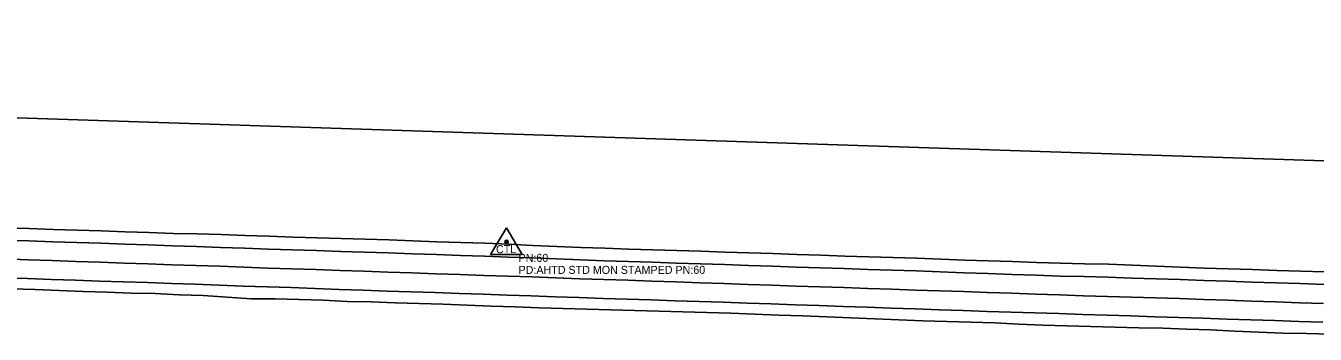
# Model space of a CAD drawing. Extents: x 976456 to 985170, y 1525951 to 1527080.
# Drawn here: x 980813 to 981619, y 1526356 to 1526549 of the extents above; entities that cross this region are included whole.
import ezdxf

# ---------------------------------------------------------------- set-up
doc = ezdxf.new("R2010")
doc.units = 0
for name, color, linetype in [('S_EDGE_PAVEMENT', 7, 'Continuous'), ('S_FIBER_OPTIC_CABLE', 7, 'Continuous'), ('S_PAVEMENT_CROWN', 7, 'Continuous'), ('S_PRIMARY_CTL', 7, 'Continuous'), ('S_PRIMARY_CTL_ANNOT', 7, 'Continuous'), ('S_SHOULDER', 7, 'Continuous')]:
    doc.layers.add(name, color=color, linetype=linetype)

msp = doc.modelspace()

# ---------------------------------------------------------------- linework, layer by layer
at = {"layer": 'S_EDGE_PAVEMENT'}
for points in [[(980799.88, 1526414.86), (980814.87, 1526414.33), (980829.86, 1526413.87), (980829.86, 1526413.87), (980844.85, 1526413.33), (980844.85, 1526413.33), (980859.84, 1526412.94), (980874.84, 1526412.4), (980874.84, 1526412.4), (980889.81, 1526411.88), (980904.8, 1526411.37), (980919.79, 1526410.8), (980919.79, 1526410.8), (980934.78, 1526410.32), (980949.77, 1526409.81), (980964.76, 1526409.28), (980964.76, 1526409.28), (980979.76, 1526408.77), (980994.75, 1526408.3), (980994.75, 1526408.3), (981009.74, 1526407.81), (981024.73, 1526407.32), (981039.68, 1526406.84), (981054.67, 1526406.31), (981069.66, 1526405.78), (981084.66, 1526405.32), (981099.65, 1526404.85), (981114.64, 1526404.28), (981114.64, 1526404.28), (981129.63, 1526403.7), (981144.62, 1526403.14), (981159.68, 1526402.54), (981174.67, 1526401.99), (981189.66, 1526401.51), (981204.65, 1526401.01), (981219.65, 1526400.55), (981234.64, 1526400.06), (981249.63, 1526399.55), (981264.62, 1526399.1), (981279.61, 1526398.56), (981294.6, 1526398.01), (981309.59, 1526397.5), (981324.54, 1526397.04), (981339.53, 1526396.61), (981354.52, 1526396.11), (981369.52, 1526395.62), (981384.51, 1526395.13), (981399.49, 1526394.52), (981414.49, 1526393.99), (981429.47, 1526393.42), (981444.47, 1526392.93), (981459.46, 1526392.44), (981474.43, 1526392.06), (981489.42, 1526391.62), (981504.41, 1526391.12), (981519.41, 1526390.68), (981519.41, 1526390.68), (981534.4, 1526390.2), (981534.4, 1526390.2), (981549.39, 1526389.63), (981564.38, 1526389.15), (981579.37, 1526388.69), (981594.45, 1526388.2), (981609.44, 1526387.73), (981624.43, 1526387.21)], [(980799.04, 1526391.32), (980814.03, 1526390.79), (980829.02, 1526390.26), (980844.01, 1526389.8), (980859, 1526389.31), (980859, 1526389.31), (980873.99, 1526388.82), (980889, 1526388.32), (980889, 1526388.32), (980903.99, 1526387.78), (980918.98, 1526387.26), (980933.97, 1526386.71), (980948.96, 1526386.18), (980963.96, 1526385.69), (980978.95, 1526385.17), (980978.95, 1526385.17), (980993.94, 1526384.64), (981008.93, 1526384.1), (981008.93, 1526384.1), (981023.92, 1526383.58), (981023.92, 1526383.58), (981038.95, 1526383.07), (981053.94, 1526382.58), (981053.94, 1526382.58), (981068.93, 1526382.07), (981068.93, 1526382.07), (981083.92, 1526381.59), (981083.92, 1526381.59), (981098.91, 1526381.01), (981098.91, 1526381.01), (981113.9, 1526380.49), (981113.9, 1526380.49), (981128.89, 1526379.96), (981143.88, 1526379.46), (981143.88, 1526379.46), (981158.81, 1526378.95), (981158.81, 1526378.95), (981173.8, 1526378.44), (981188.8, 1526377.95), (981203.79, 1526377.46), (981218.78, 1526376.96), (981233.77, 1526376.52), (981248.77, 1526376.02), (981263.76, 1526375.47), (981263.76, 1526375.47), (981278.75, 1526374.96), (981293.74, 1526374.44), (981293.74, 1526374.44), (981308.73, 1526373.92), (981323.76, 1526373.43), (981323.76, 1526373.43), (981338.76, 1526372.95), (981338.76, 1526372.95), (981353.75, 1526372.45), (981368.74, 1526371.96), (981383.73, 1526371.4), (981398.72, 1526370.85), (981398.72, 1526370.85), (981413.71, 1526370.34), (981428.7, 1526369.85), (981443.7, 1526369.39), (981458.69, 1526368.92), (981458.69, 1526368.92), (981473.7, 1526368.46), (981473.7, 1526368.46), (981488.7, 1526368.01), (981488.7, 1526368.01), (981503.69, 1526367.51), (981518.68, 1526367.03), (981533.67, 1526366.53), (981548.67, 1526366.05), (981563.66, 1526365.57), (981578.65, 1526365.1), (981593.58, 1526364.6), (981593.58, 1526364.6), (981608.57, 1526364.09), (981608.57, 1526364.09), (981623.56, 1526363.57)]]:
    msp.add_lwpolyline(points, dxfattribs=at)
at = {"layer": 'S_FIBER_OPTIC_CABLE'}
msp.add_line((982227.16, 1526444.43), (979068.74, 1526548.75), dxfattribs=at)
at = {"layer": 'S_PAVEMENT_CROWN'}
msp.add_lwpolyline([(980799.46, 1526403.07), (980814.45, 1526402.54), (980814.45, 1526402.54), (980829.44, 1526402.06), (980844.43, 1526401.52), (980859.42, 1526401.01), (980874.41, 1526400.45), (980874.41, 1526400.45), (980889.4, 1526399.96), (980904.39, 1526399.51), (980904.39, 1526399.51), (980919.39, 1526399), (980934.38, 1526398.49), (980949.37, 1526397.96), (980949.37, 1526397.96), (980964.36, 1526397.44), (980964.36, 1526397.44), (980979.35, 1526396.92), (980979.35, 1526396.92), (980994.34, 1526396.41), (980994.34, 1526396.41), (981009.33, 1526395.9), (981009.33, 1526395.9), (981024.32, 1526395.39), (981024.32, 1526395.39), (981039.31, 1526394.91), (981054.31, 1526394.45), (981054.31, 1526394.45), (981069.29, 1526393.85), (981069.29, 1526393.85), (981084.28, 1526393.31), (981084.28, 1526393.31), (981099.28, 1526392.84), (981099.28, 1526392.84), (981114.27, 1526392.38), (981129.26, 1526391.92), (981144.25, 1526391.24), (981144.25, 1526391.24), (981159.24, 1526390.74), (981159.24, 1526390.74), (981174.23, 1526390.19), (981174.23, 1526390.19), (981189.23, 1526389.76), (981189.23, 1526389.76), (981204.22, 1526389.21), (981204.22, 1526389.21), (981219.21, 1526388.72), (981234.2, 1526388.19), (981234.2, 1526388.19), (981249.2, 1526387.7), (981249.2, 1526387.7), (981264.19, 1526387.2), (981264.19, 1526387.2), (981279.18, 1526386.71), (981294.17, 1526386.14), (981294.17, 1526386.14), (981309.17, 1526385.78), (981309.17, 1526385.78), (981324.15, 1526385.3), (981324.15, 1526385.3), (981339.14, 1526384.74), (981354.13, 1526384.18), (981369.12, 1526383.69), (981369.12, 1526383.69), (981384.11, 1526383.19), (981384.11, 1526383.19), (981399.11, 1526382.7), (981399.11, 1526382.7), (981414.1, 1526382.15), (981414.1, 1526382.15), (981429.09, 1526381.66), (981429.09, 1526381.66), (981444.08, 1526381.16), (981444.08, 1526381.16), (981459.07, 1526380.69), (981459.07, 1526380.69), (981474.06, 1526380.16), (981489.06, 1526379.69), (981504.05, 1526379.23), (981504.05, 1526379.23), (981519.04, 1526378.77), (981534.04, 1526378.34), (981534.04, 1526378.34), (981549.03, 1526377.8), (981564.02, 1526377.25), (981564.02, 1526377.25), (981579.01, 1526376.79), (981579.01, 1526376.79), (981594.01, 1526376.31), (981594.01, 1526376.31), (981609, 1526375.76), (981609, 1526375.76), (981623.99, 1526375.25)], dxfattribs=at)
at = {"layer": 'S_PRIMARY_CTL'}
for p, q in [((981113.46, 1526422.49), (981103.43, 1526405.98)), ((981113.46, 1526422.49), (981123.29, 1526405.98)), ((981103.43, 1526405.98), (981123.29, 1526405.98))]:
    msp.add_line(p, q, dxfattribs=at)
for radius in [1.04, 0.609, 0.344]:
    msp.add_circle((981113.46, 1526413.79), radius, dxfattribs=at)
at = {"layer": 'S_SHOULDER'}
for points in [[(980800.15, 1526422.55), (980815.14, 1526422.02), (980830.14, 1526421.55), (980845.13, 1526421.02), (980860.12, 1526420.62), (980875.11, 1526420.05), (980890.08, 1526419.53), (980905.07, 1526419.01), (980920.06, 1526418.71), (980935.06, 1526418.28), (980950.05, 1526417.79), (980965.04, 1526417.25), (980980.03, 1526416.79), (980995.03, 1526416.32), (981010.02, 1526415.8), (981025.02, 1526415.46), (981039.94, 1526414.98), (981054.93, 1526414.45), (981069.92, 1526413.83), (981084.91, 1526413.36), (981099.9, 1526412.9), (981114.89, 1526412.33), (981129.87, 1526411.51), (981144.86, 1526410.87), (981159.97, 1526410.27), (981174.96, 1526409.74), (981189.95, 1526409.29), (981204.94, 1526408.78), (981219.94, 1526408.35), (981234.93, 1526407.89), (981249.92, 1526407.39), (981264.92, 1526406.93), (981279.91, 1526406.43), (981294.9, 1526405.88), (981309.89, 1526405.37), (981324.8, 1526404.93), (981339.79, 1526404.49), (981354.79, 1526404), (981369.78, 1526403.51), (981384.77, 1526403.02), (981399.76, 1526402.41), (981414.75, 1526401.88), (981429.74, 1526401.43), (981444.73, 1526400.93), (981459.73, 1526400.44), (981474.68, 1526400.14), (981489.68, 1526399.79), (981504.67, 1526399.3), (981519.66, 1526398.68), (981534.64, 1526397.94), (981549.63, 1526397.37), (981564.62, 1526396.9), (981579.61, 1526396.44), (981594.74, 1526395.95), (981609.73, 1526395.48), (981624.72, 1526394.96)], [(980803.93, 1526384.47), (980818.92, 1526383.93), (980833.91, 1526383.4), (980848.9, 1526382.81), (980863.89, 1526382.28), (980878.9, 1526381.65), (980893.91, 1526381.55), (980908.89, 1526380.77), (980923.88, 1526380.25), (980938.85, 1526379.17), (980953.83, 1526378.19), (980968.83, 1526378.12), (980983.83, 1526377.82), (980998.82, 1526377.3), (981013.81, 1526376.61), (981028.86, 1526376.26), (981043.85, 1526375.76), (981058.85, 1526375.27), (981073.84, 1526374.81), (981088.83, 1526374.33), (981103.82, 1526373.66), (981118.81, 1526373.19), (981133.8, 1526372.62), (981148.79, 1526372.16), (981163.68, 1526371.63), (981178.68, 1526371.23), (981193.68, 1526370.96), (981208.67, 1526370.48), (981223.66, 1526370.04), (981238.66, 1526369.73), (981253.66, 1526369.29), (981268.64, 1526368.65), (981283.63, 1526367.95), (981298.62, 1526367.52), (981313.68, 1526367.02), (981328.67, 1526366.42), (981343.66, 1526365.77), (981358.64, 1526365.1), (981373.63, 1526364.4), (981388.62, 1526363.97), (981403.62, 1526363.7), (981418.61, 1526363.12), (981433.59, 1526362.45), (981448.58, 1526361.75), (981463.57, 1526361.27), (981478.61, 1526360.93), (981493.6, 1526360.5), (981508.6, 1526360.1), (981523.59, 1526359.76), (981538.58, 1526359.24), (981553.58, 1526358.78), (981568.56, 1526357.99), (981583.55, 1526357.3), (981598.42, 1526356.71), (981613.42, 1526356.43), (981628.42, 1526356.09)]]:
    msp.add_lwpolyline(points, dxfattribs=at)

# ---------------------------------------------------------------- texts
at = {"layer": 'S_PRIMARY_CTL'}
msp.add_text('CTL', height=5, rotation=360, dxfattribs=at).set_placement((981106.88, 1526406.72))
at = {"layer": 'S_PRIMARY_CTL_ANNOT'}
for s, p in [('PN:60', (981120.96, 1526401.29)), ('PD:AHTD STD MON STAMPED PN:60', (981120.96, 1526393.79))]:
    msp.add_text(s, height=5, dxfattribs=at).set_placement(p)

doc.saveas('drawing.dxf')
